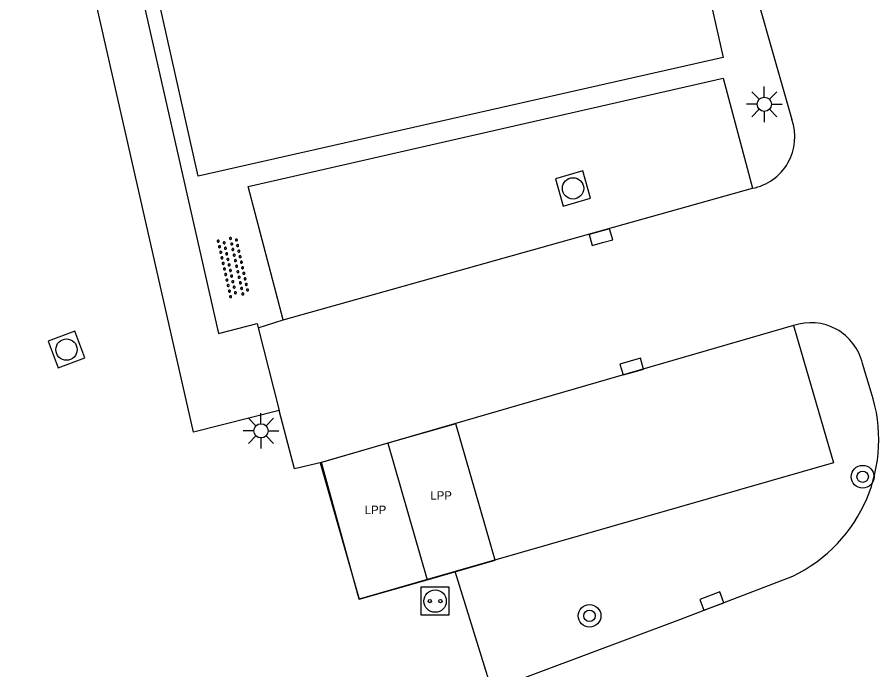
# Model space of a CAD drawing. Extents: x 137999 to 141000, y 397500 to 400501.
# Drawn here: x 138312.22 to 138342.52, y 399235.95 to 399258.89 of the extents above; entities that cross this region are included whole.
import ezdxf

# ---------------------------------------------------------------- set-up
doc = ezdxf.new("R2010")
doc.units = 0
for name, color, linetype in [('bp-grn-parkeervak', 7, 'Continuous'), ('gg-bbg-hoofdgebouw', 7, 'Continuous'), ('gg-knt-verharding', 7, 'Continuous'), ('gg-knt-verharding nz', 7, 'Continuous'), ('gt-grn-groengrens', 7, 'Continuous'), ('gt-symb-boom', 7, 'Continuous'), ('gt-symb-kolk', 7, 'Continuous'), ('gt-symb-laadpunt elektrisch vervoer', 7, 'Continuous'), ('gt-symb-lichtmast', 7, 'Continuous'), ('gt-symb-overige verharding', 7, 'Continuous'), ('gt-symb-rioolschacht', 7, 'Continuous'), ('kenmerkpunt laadpunt parkeerplaats', 7, 'Continuous')]:
    doc.layers.add(name, color=color, linetype=linetype)

# ---------------------------------------------------------------- blocks, each defined once
blk = doc.blocks.new('gt0-RS')
at = {"layer": 'gt-symb-rioolschacht'}
blk.add_lwpolyline([(-0.5, -0.5), (0.5, -0.5), (0.5, 0.5), (-0.5, 0.5)], close=True, dxfattribs=at)
blk.add_circle((0, 0), 0.375, dxfattribs=at)
blk = doc.blocks.new('gt0-KOLK')
at = {"layer": 'gt-symb-kolk'}
blk.add_lwpolyline([(0, 0), (0.375, 0), (0.375, 0.4), (-0.375, 0.4), (-0.375, 0), (0, 0)], dxfattribs=at)
blk = doc.blocks.new('gt0-LMAST')
at = {"layer": 'gt-symb-lichtmast'}
for p, q in [((-0.005, 0.246), (-0.005, 0.621)), ((-0.182, 0.173), (-0.447, 0.438)), ((0.172, 0.173), (0.437, 0.438)), ((-0.255, -0.004), (-0.63, -0.004)), ((-0.182, -0.181), (-0.447, -0.446)), ((-0.005, -0.254), (-0.005, -0.629)), ((0.437, -0.446), (0.172, -0.181)), ((0.245, -0.004), (0.62, -0.004))]:
    blk.add_line(p, q, dxfattribs=at)
blk.add_circle((-0.005, -0.004), 0.25, dxfattribs=at)
blk = doc.blocks.new('gt0-OVH')
at = {"layer": 'gt-symb-overige verharding'}
for points in [[(-0.972, 0.298), (-0.967, 0.308), (-0.965, 0.319), (-0.966, 0.33), (-0.971, 0.34), (-0.978, 0.348), (-0.988, 0.353), (-0.999, 0.355), (-1.01, 0.354), (-1.02, 0.349), (-1.028, 0.342), (-1.033, 0.332), (-1.035, 0.321), (-1.034, 0.31), (-1.029, 0.3), (-1.022, 0.292), (-1.012, 0.287), (-1.001, 0.285), (-0.99, 0.286), (-0.98, 0.291)], [(-0.772, 0.298), (-0.767, 0.308), (-0.765, 0.319), (-0.766, 0.33), (-0.771, 0.34), (-0.778, 0.348), (-0.788, 0.353), (-0.799, 0.355), (-0.81, 0.354), (-0.82, 0.349), (-0.828, 0.342), (-0.833, 0.332), (-0.835, 0.321), (-0.834, 0.31), (-0.829, 0.3), (-0.822, 0.292), (-0.812, 0.287), (-0.801, 0.285), (-0.79, 0.286), (-0.78, 0.291)], [(-0.572, 0.298), (-0.567, 0.308), (-0.565, 0.319), (-0.566, 0.33), (-0.571, 0.34), (-0.578, 0.348), (-0.588, 0.353), (-0.599, 0.355), (-0.61, 0.354), (-0.62, 0.349), (-0.628, 0.342), (-0.633, 0.332), (-0.635, 0.321), (-0.634, 0.31), (-0.629, 0.3), (-0.622, 0.292), (-0.612, 0.287), (-0.601, 0.285), (-0.59, 0.286), (-0.58, 0.291)], [(-0.372, 0.298), (-0.367, 0.308), (-0.365, 0.319), (-0.366, 0.33), (-0.371, 0.34), (-0.378, 0.348), (-0.388, 0.353), (-0.399, 0.355), (-0.41, 0.354), (-0.42, 0.349), (-0.428, 0.342), (-0.433, 0.332), (-0.435, 0.321), (-0.434, 0.31), (-0.429, 0.3), (-0.422, 0.292), (-0.412, 0.287), (-0.401, 0.285), (-0.39, 0.286), (-0.38, 0.291)], [(-0.172, 0.298), (-0.167, 0.308), (-0.165, 0.319), (-0.166, 0.33), (-0.171, 0.34), (-0.178, 0.348), (-0.188, 0.353), (-0.199, 0.355), (-0.21, 0.354), (-0.22, 0.349), (-0.228, 0.342), (-0.233, 0.332), (-0.235, 0.321), (-0.234, 0.31), (-0.229, 0.3), (-0.222, 0.292), (-0.212, 0.287), (-0.201, 0.285), (-0.19, 0.286), (-0.18, 0.291)], [(0.028, 0.298), (0.033, 0.308), (0.035, 0.319), (0.034, 0.33), (0.029, 0.34), (0.022, 0.348), (0.012, 0.353), (0.001, 0.355), (-0.01, 0.354), (-0.02, 0.349), (-0.028, 0.342), (-0.033, 0.332), (-0.035, 0.321), (-0.034, 0.31), (-0.029, 0.3), (-0.022, 0.292), (-0.012, 0.287), (-0.001, 0.285), (0.01, 0.286), (0.02, 0.291)], [(0.228, 0.298), (0.233, 0.308), (0.235, 0.319), (0.234, 0.33), (0.229, 0.34), (0.222, 0.348), (0.212, 0.353), (0.201, 0.355), (0.19, 0.354), (0.18, 0.349), (0.172, 0.342), (0.167, 0.332), (0.165, 0.321), (0.166, 0.31), (0.171, 0.3), (0.178, 0.292), (0.188, 0.287), (0.199, 0.285), (0.21, 0.286), (0.22, 0.291)], [(0.428, 0.298), (0.433, 0.308), (0.435, 0.319), (0.434, 0.33), (0.429, 0.34), (0.422, 0.348), (0.412, 0.353), (0.401, 0.355), (0.39, 0.354), (0.38, 0.349), (0.372, 0.342), (0.367, 0.332), (0.365, 0.321), (0.366, 0.31), (0.371, 0.3), (0.378, 0.292), (0.388, 0.287), (0.399, 0.285), (0.41, 0.286), (0.42, 0.291)], [(0.628, 0.298), (0.633, 0.308), (0.635, 0.319), (0.634, 0.33), (0.629, 0.34), (0.622, 0.348), (0.612, 0.353), (0.601, 0.355), (0.59, 0.354), (0.58, 0.349), (0.572, 0.342), (0.567, 0.332), (0.565, 0.321), (0.566, 0.31), (0.571, 0.3), (0.578, 0.292), (0.588, 0.287), (0.599, 0.285), (0.61, 0.286), (0.62, 0.291)], [(0.828, 0.298), (0.833, 0.308), (0.835, 0.319), (0.834, 0.33), (0.829, 0.34), (0.822, 0.348), (0.812, 0.353), (0.801, 0.355), (0.79, 0.354), (0.78, 0.349), (0.772, 0.342), (0.767, 0.332), (0.765, 0.321), (0.766, 0.31), (0.771, 0.3), (0.778, 0.292), (0.788, 0.287), (0.799, 0.285), (0.81, 0.286), (0.82, 0.291)], [(1.028, 0.298), (1.033, 0.308), (1.035, 0.319), (1.034, 0.33), (1.029, 0.34), (1.022, 0.348), (1.012, 0.353), (1.001, 0.355), (0.99, 0.354), (0.98, 0.349), (0.972, 0.342), (0.967, 0.332), (0.965, 0.321), (0.966, 0.31), (0.971, 0.3), (0.978, 0.292), (0.988, 0.287), (0.999, 0.285), (1.01, 0.286), (1.02, 0.291)], [(-0.872, 0.106), (-0.867, 0.116), (-0.865, 0.126), (-0.866, 0.137), (-0.871, 0.147), (-0.878, 0.156), (-0.888, 0.161), (-0.899, 0.163), (-0.91, 0.162), (-0.92, 0.157), (-0.928, 0.15), (-0.933, 0.14), (-0.935, 0.129), (-0.934, 0.118), (-0.929, 0.108), (-0.922, 0.1), (-0.912, 0.095), (-0.901, 0.092), (-0.89, 0.094), (-0.88, 0.098)], [(-0.672, 0.106), (-0.667, 0.116), (-0.665, 0.126), (-0.666, 0.137), (-0.671, 0.147), (-0.678, 0.156), (-0.688, 0.161), (-0.699, 0.163), (-0.71, 0.162), (-0.72, 0.157), (-0.728, 0.15), (-0.733, 0.14), (-0.735, 0.129), (-0.734, 0.118), (-0.729, 0.108), (-0.722, 0.1), (-0.712, 0.095), (-0.701, 0.092), (-0.69, 0.094), (-0.68, 0.098)], [(-0.472, 0.106), (-0.467, 0.116), (-0.465, 0.126), (-0.466, 0.137), (-0.471, 0.147), (-0.478, 0.156), (-0.488, 0.161), (-0.499, 0.163), (-0.51, 0.162), (-0.52, 0.157), (-0.528, 0.15), (-0.533, 0.14), (-0.535, 0.129), (-0.534, 0.118), (-0.529, 0.108), (-0.522, 0.1), (-0.512, 0.095), (-0.501, 0.092), (-0.49, 0.094), (-0.48, 0.098)], [(-0.272, 0.106), (-0.267, 0.116), (-0.265, 0.126), (-0.266, 0.137), (-0.271, 0.147), (-0.278, 0.156), (-0.288, 0.161), (-0.299, 0.163), (-0.31, 0.162), (-0.32, 0.157), (-0.328, 0.15), (-0.333, 0.14), (-0.335, 0.129), (-0.334, 0.118), (-0.329, 0.108), (-0.322, 0.1), (-0.312, 0.095), (-0.301, 0.092), (-0.29, 0.094), (-0.28, 0.098)], [(-0.072, 0.106), (-0.067, 0.116), (-0.065, 0.126), (-0.066, 0.137), (-0.071, 0.147), (-0.078, 0.156), (-0.088, 0.161), (-0.099, 0.163), (-0.11, 0.162), (-0.12, 0.157), (-0.128, 0.15), (-0.133, 0.14), (-0.135, 0.129), (-0.134, 0.118), (-0.129, 0.108), (-0.122, 0.1), (-0.112, 0.095), (-0.101, 0.092), (-0.09, 0.094), (-0.08, 0.098)], [(0.128, 0.106), (0.133, 0.116), (0.135, 0.126), (0.134, 0.137), (0.129, 0.147), (0.122, 0.156), (0.112, 0.161), (0.101, 0.163), (0.09, 0.162), (0.08, 0.157), (0.072, 0.15), (0.067, 0.14), (0.065, 0.129), (0.066, 0.118), (0.071, 0.108), (0.078, 0.1), (0.088, 0.095), (0.099, 0.092), (0.11, 0.094), (0.12, 0.098)], [(0.328, 0.106), (0.333, 0.116), (0.335, 0.126), (0.334, 0.137), (0.329, 0.147), (0.322, 0.156), (0.312, 0.161), (0.301, 0.163), (0.29, 0.162), (0.28, 0.157), (0.272, 0.15), (0.267, 0.14), (0.265, 0.129), (0.266, 0.118), (0.271, 0.108), (0.278, 0.1), (0.288, 0.095), (0.299, 0.092), (0.31, 0.094), (0.32, 0.098)], [(0.528, 0.106), (0.533, 0.116), (0.535, 0.126), (0.534, 0.137), (0.529, 0.147), (0.522, 0.156), (0.512, 0.161), (0.501, 0.163), (0.49, 0.162), (0.48, 0.157), (0.472, 0.15), (0.467, 0.14), (0.465, 0.129), (0.466, 0.118), (0.471, 0.108), (0.478, 0.1), (0.488, 0.095), (0.499, 0.092), (0.51, 0.094), (0.52, 0.098)], [(0.728, 0.106), (0.733, 0.116), (0.735, 0.126), (0.734, 0.137), (0.729, 0.147), (0.722, 0.156), (0.712, 0.161), (0.701, 0.163), (0.69, 0.162), (0.68, 0.157), (0.672, 0.15), (0.667, 0.14), (0.665, 0.129), (0.666, 0.118), (0.671, 0.108), (0.678, 0.1), (0.688, 0.095), (0.699, 0.092), (0.71, 0.094), (0.72, 0.098)], [(0.928, 0.106), (0.933, 0.116), (0.935, 0.126), (0.934, 0.137), (0.929, 0.147), (0.922, 0.156), (0.912, 0.161), (0.901, 0.163), (0.89, 0.162), (0.88, 0.157), (0.872, 0.15), (0.867, 0.14), (0.865, 0.129), (0.866, 0.118), (0.871, 0.108), (0.878, 0.1), (0.888, 0.095), (0.899, 0.092), (0.91, 0.094), (0.92, 0.098)], [(-0.972, -0.142), (-0.967, -0.132), (-0.965, -0.121), (-0.966, -0.11), (-0.971, -0.1), (-0.978, -0.092), (-0.988, -0.087), (-0.999, -0.085), (-1.01, -0.086), (-1.02, -0.091), (-1.028, -0.098), (-1.033, -0.108), (-1.035, -0.119), (-1.034, -0.13), (-1.029, -0.14), (-1.022, -0.148), (-1.012, -0.153), (-1.001, -0.155), (-0.99, -0.154), (-0.98, -0.149)], [(-0.872, -0.334), (-0.867, -0.324), (-0.865, -0.314), (-0.866, -0.303), (-0.871, -0.293), (-0.878, -0.284), (-0.888, -0.279), (-0.899, -0.277), (-0.91, -0.278), (-0.92, -0.283), (-0.928, -0.29), (-0.933, -0.3), (-0.935, -0.311), (-0.934, -0.322), (-0.929, -0.332), (-0.922, -0.34), (-0.912, -0.345), (-0.901, -0.348), (-0.89, -0.346), (-0.88, -0.342)], [(-0.772, -0.142), (-0.767, -0.132), (-0.765, -0.121), (-0.766, -0.11), (-0.771, -0.1), (-0.778, -0.092), (-0.788, -0.087), (-0.799, -0.085), (-0.81, -0.086), (-0.82, -0.091), (-0.828, -0.098), (-0.833, -0.108), (-0.835, -0.119), (-0.834, -0.13), (-0.829, -0.14), (-0.822, -0.148), (-0.812, -0.153), (-0.801, -0.155), (-0.79, -0.154), (-0.78, -0.149)], [(-0.672, -0.334), (-0.667, -0.324), (-0.665, -0.314), (-0.666, -0.303), (-0.671, -0.293), (-0.678, -0.284), (-0.688, -0.279), (-0.699, -0.277), (-0.71, -0.278), (-0.72, -0.283), (-0.728, -0.29), (-0.733, -0.3), (-0.735, -0.311), (-0.734, -0.322), (-0.729, -0.332), (-0.722, -0.34), (-0.712, -0.345), (-0.701, -0.348), (-0.69, -0.346), (-0.68, -0.342)], [(-0.572, -0.142), (-0.567, -0.132), (-0.565, -0.121), (-0.566, -0.11), (-0.571, -0.1), (-0.578, -0.092), (-0.588, -0.087), (-0.599, -0.085), (-0.61, -0.086), (-0.62, -0.091), (-0.628, -0.098), (-0.633, -0.108), (-0.635, -0.119), (-0.634, -0.13), (-0.629, -0.14), (-0.622, -0.148), (-0.612, -0.153), (-0.601, -0.155), (-0.59, -0.154), (-0.58, -0.149)], [(-0.472, -0.334), (-0.467, -0.324), (-0.465, -0.314), (-0.466, -0.303), (-0.471, -0.293), (-0.478, -0.284), (-0.488, -0.279), (-0.499, -0.277), (-0.51, -0.278), (-0.52, -0.283), (-0.528, -0.29), (-0.533, -0.3), (-0.535, -0.311), (-0.534, -0.322), (-0.529, -0.332), (-0.522, -0.34), (-0.512, -0.345), (-0.501, -0.348), (-0.49, -0.346), (-0.48, -0.342)], [(-0.372, -0.142), (-0.367, -0.132), (-0.365, -0.121), (-0.366, -0.11), (-0.371, -0.1), (-0.378, -0.092), (-0.388, -0.087), (-0.399, -0.085), (-0.41, -0.086), (-0.42, -0.091), (-0.428, -0.098), (-0.433, -0.108), (-0.435, -0.119), (-0.434, -0.13), (-0.429, -0.14), (-0.422, -0.148), (-0.412, -0.153), (-0.401, -0.155), (-0.39, -0.154), (-0.38, -0.149)], [(-0.272, -0.334), (-0.267, -0.324), (-0.265, -0.314), (-0.266, -0.303), (-0.271, -0.293), (-0.278, -0.284), (-0.288, -0.279), (-0.299, -0.277), (-0.31, -0.278), (-0.32, -0.283), (-0.328, -0.29), (-0.333, -0.3), (-0.335, -0.311), (-0.334, -0.322), (-0.329, -0.332), (-0.322, -0.34), (-0.312, -0.345), (-0.301, -0.348), (-0.29, -0.346), (-0.28, -0.342)], [(-0.172, -0.142), (-0.167, -0.132), (-0.165, -0.121), (-0.166, -0.11), (-0.171, -0.1), (-0.178, -0.092), (-0.188, -0.087), (-0.199, -0.085), (-0.21, -0.086), (-0.22, -0.091), (-0.228, -0.098), (-0.233, -0.108), (-0.235, -0.119), (-0.234, -0.13), (-0.229, -0.14), (-0.222, -0.148), (-0.212, -0.153), (-0.201, -0.155), (-0.19, -0.154), (-0.18, -0.149)], [(-0.072, -0.334), (-0.067, -0.324), (-0.065, -0.314), (-0.066, -0.303), (-0.071, -0.293), (-0.078, -0.284), (-0.088, -0.279), (-0.099, -0.277), (-0.11, -0.278), (-0.12, -0.283), (-0.128, -0.29), (-0.133, -0.3), (-0.135, -0.311), (-0.134, -0.322), (-0.129, -0.332), (-0.122, -0.34), (-0.112, -0.345), (-0.101, -0.348), (-0.09, -0.346), (-0.08, -0.342)], [(0.028, -0.142), (0.033, -0.132), (0.035, -0.121), (0.034, -0.11), (0.029, -0.1), (0.022, -0.092), (0.012, -0.087), (0.001, -0.085), (-0.01, -0.086), (-0.02, -0.091), (-0.028, -0.098), (-0.033, -0.108), (-0.035, -0.119), (-0.034, -0.13), (-0.029, -0.14), (-0.022, -0.148), (-0.012, -0.153), (-0.001, -0.155), (0.01, -0.154), (0.02, -0.149)], [(0.128, -0.334), (0.133, -0.324), (0.135, -0.314), (0.134, -0.303), (0.129, -0.293), (0.122, -0.284), (0.112, -0.279), (0.101, -0.277), (0.09, -0.278), (0.08, -0.283), (0.072, -0.29), (0.067, -0.3), (0.065, -0.311), (0.066, -0.322), (0.071, -0.332), (0.078, -0.34), (0.088, -0.345), (0.099, -0.348), (0.11, -0.346), (0.12, -0.342)], [(0.228, -0.142), (0.233, -0.132), (0.235, -0.121), (0.234, -0.11), (0.229, -0.1), (0.222, -0.092), (0.212, -0.087), (0.201, -0.085), (0.19, -0.086), (0.18, -0.091), (0.172, -0.098), (0.167, -0.108), (0.165, -0.119), (0.166, -0.13), (0.171, -0.14), (0.178, -0.148), (0.188, -0.153), (0.199, -0.155), (0.21, -0.154), (0.22, -0.149)], [(0.328, -0.334), (0.333, -0.324), (0.335, -0.314), (0.334, -0.303), (0.329, -0.293), (0.322, -0.284), (0.312, -0.279), (0.301, -0.277), (0.29, -0.278), (0.28, -0.283), (0.272, -0.29), (0.267, -0.3), (0.265, -0.311), (0.266, -0.322), (0.271, -0.332), (0.278, -0.34), (0.288, -0.345), (0.299, -0.348), (0.31, -0.346), (0.32, -0.342)], [(0.428, -0.142), (0.433, -0.132), (0.435, -0.121), (0.434, -0.11), (0.429, -0.1), (0.422, -0.092), (0.412, -0.087), (0.401, -0.085), (0.39, -0.086), (0.38, -0.091), (0.372, -0.098), (0.367, -0.108), (0.365, -0.119), (0.366, -0.13), (0.371, -0.14), (0.378, -0.148), (0.388, -0.153), (0.399, -0.155), (0.41, -0.154), (0.42, -0.149)], [(0.528, -0.334), (0.533, -0.324), (0.535, -0.314), (0.534, -0.303), (0.529, -0.293), (0.522, -0.284), (0.512, -0.279), (0.501, -0.277), (0.49, -0.278), (0.48, -0.283), (0.472, -0.29), (0.467, -0.3), (0.465, -0.311), (0.466, -0.322), (0.471, -0.332), (0.478, -0.34), (0.488, -0.345), (0.499, -0.348), (0.51, -0.346), (0.52, -0.342)], [(0.628, -0.142), (0.633, -0.132), (0.635, -0.121), (0.634, -0.11), (0.629, -0.1), (0.622, -0.092), (0.612, -0.087), (0.601, -0.085), (0.59, -0.086), (0.58, -0.091), (0.572, -0.098), (0.567, -0.108), (0.565, -0.119), (0.566, -0.13), (0.571, -0.14), (0.578, -0.148), (0.588, -0.153), (0.599, -0.155), (0.61, -0.154), (0.62, -0.149)], [(0.728, -0.334), (0.733, -0.324), (0.735, -0.314), (0.734, -0.303), (0.729, -0.293), (0.722, -0.284), (0.712, -0.279), (0.701, -0.277), (0.69, -0.278), (0.68, -0.283), (0.672, -0.29), (0.667, -0.3), (0.665, -0.311), (0.666, -0.322), (0.671, -0.332), (0.678, -0.34), (0.688, -0.345), (0.699, -0.348), (0.71, -0.346), (0.72, -0.342)], [(0.828, -0.142), (0.833, -0.132), (0.835, -0.121), (0.834, -0.11), (0.829, -0.1), (0.822, -0.092), (0.812, -0.087), (0.801, -0.085), (0.79, -0.086), (0.78, -0.091), (0.772, -0.098), (0.767, -0.108), (0.765, -0.119), (0.766, -0.13), (0.771, -0.14), (0.778, -0.148), (0.788, -0.153), (0.799, -0.155), (0.81, -0.154), (0.82, -0.149)], [(0.928, -0.334), (0.933, -0.324), (0.935, -0.314), (0.934, -0.303), (0.929, -0.293), (0.922, -0.284), (0.912, -0.279), (0.901, -0.277), (0.89, -0.278), (0.88, -0.283), (0.872, -0.29), (0.867, -0.3), (0.865, -0.311), (0.866, -0.322), (0.871, -0.332), (0.878, -0.34), (0.888, -0.345), (0.899, -0.348), (0.91, -0.346), (0.92, -0.342)], [(1.028, -0.142), (1.033, -0.132), (1.035, -0.121), (1.034, -0.11), (1.029, -0.1), (1.022, -0.092), (1.012, -0.087), (1.001, -0.085), (0.99, -0.086), (0.98, -0.091), (0.972, -0.098), (0.967, -0.108), (0.965, -0.119), (0.966, -0.13), (0.971, -0.14), (0.978, -0.148), (0.988, -0.153), (0.999, -0.155), (1.01, -0.154), (1.02, -0.149)]]:
    blk.add_lwpolyline(points, close=True, dxfattribs=at)
blk = doc.blocks.new('gt0-BOOM')
at = {"layer": 'gt-symb-boom'}
for radius in [0.4, 0.2]:
    blk.add_circle((0, 0), radius, dxfattribs=at)
blk = doc.blocks.new('gt0-LEV')
at = {"layer": 'gt-symb-laadpunt elektrisch vervoer'}
blk.add_lwpolyline([(-0.486, 0.501), (0.486, 0.501), (0.486, -0.499), (-0.486, -0.499)], close=True, dxfattribs=at)
for centre, radius in [((0, 0), 0.393), ((-0.186, 0), 0.0566), ((0.186, 0), 0.0566)]:
    blk.add_circle(centre, radius, dxfattribs=at)

msp = doc.modelspace()

# ---------------------------------------------------------------- linework, layer by layer
at = {"layer": 'bp-grn-parkeervak'}
msp.add_line((138325.262, 399243.911), (138326.64, 399239.117), dxfattribs=at)
for points in [[(138326.64, 399239.117), (138329.028, 399239.804), (138327.65, 399244.597), (138325.262, 399243.911)], [(138325.262, 399243.911), (138322.874, 399243.224), (138324.252, 399238.431), (138326.64, 399239.117)]]:
    msp.add_lwpolyline(points, dxfattribs=at)
at = {"layer": 'gg-bbg-hoofdgebouw'}
msp.add_lwpolyline([(138335.62, 399275.09), (138335.51, 399275.57), (138333.09, 399275.03), (138337.05, 399257.48), (138318.59, 399253.3), (138314.66, 399270.83), (138308.28, 399269.44), (138303.154, 399280.598)], dxfattribs=at)
at = {"layer": 'gg-knt-verharding'}
for p, q in [((138320.697, 399247.971), (138321.574, 399248.252)), ((138320.697, 399247.971), (138321.432, 399245.062)), ((138342.255, 399245.709), (138341.948, 399246.719))]:
    msp.add_line(p, q, dxfattribs=at)
for points in [[(138303.154, 399280.598), (138302.682, 399280.381), (138307.997, 399268.838), (138314.217, 399270.224), (138319.297, 399247.77), (138320.658, 399248.125), (138320.697, 399247.971)], [(138335.62, 399275.09), (138333.943, 399274.641), (138339.47, 399255.295)], [(138321.432, 399245.062), (138318.42, 399244.301), (138312.983, 399268.267), (138307.053, 399266.923)], [(138321.574, 399248.252), (138320.345, 399252.941), (138337.057, 399256.745), (138338.079, 399252.876)], [(138339.523, 399248.049), (138340.932, 399243.226), (138327.627, 399239.401)], [(138322.921, 399243.238), (138321.977, 399243.008), (138321.432, 399245.062)], [(138327.627, 399239.401), (138324.252, 399238.431), (138322.921, 399243.238)], [(138328.912, 399235.243), (138335.53, 399237.721), (138339.499, 399239.244)]]:
    msp.add_lwpolyline(points, dxfattribs=at)
for centre, radius, start, end in [((138337.727, 399254.688), 1.846, 281.0048, 19.1947), ((138340.135, 399246.29), 1.863, 13.3274, 109.1871), ((138337.21, 399244.04), 5.314, 295.5187, 18.3047)]:
    msp.add_arc(centre, radius, start, end, dxfattribs=at)
at = {"layer": 'gg-knt-verharding nz'}
for p, q in [((138321.574, 399248.252), (138338.079, 399252.876)), ((138339.523, 399248.049), (138325.26, 399243.916)), ((138325.26, 399243.916), (138322.921, 399243.238))]:
    msp.add_line(p, q, dxfattribs=at)
at = {"layer": 'gt-grn-groengrens'}
msp.add_line((138328.912, 399235.243), (138327.627, 399239.401), dxfattribs=at)

# ---------------------------------------------------------------- block references
at = {"layer": 'gt-symb-boom'}
for p in [(138341.958, 399242.736), (138332.352, 399237.846)]:
    msp.add_blockref('gt0-BOOM', p, dxfattribs=at)
at = {"layer": 'gt-symb-kolk'}
for p, rotation in [((138332.805, 399250.967), 15.66210634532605), ((138333.89, 399246.418), 16.13420459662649), ((138336.725, 399238.179), 20.173944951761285)]:
    msp.add_blockref('gt0-KOLK', p, dxfattribs=dict(at, rotation=rotation))
at = {"layer": 'gt-symb-laadpunt elektrisch vervoer'}
msp.add_blockref('gt0-LEV', (138326.921, 399238.364), dxfattribs=at)
at = {"layer": 'gt-symb-lichtmast'}
for p in [(138338.504, 399255.834), (138320.802, 399244.354)]:
    msp.add_blockref('gt0-LMAST', p, dxfattribs=at)
at = {"layer": 'gt-symb-overige verharding', "rotation": 102.59095061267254}
msp.add_blockref('gt0-OVH', (138319.824, 399250.112), dxfattribs=at)
at = {"layer": 'gt-symb-rioolschacht'}
for p, rotation in [((138331.771, 399252.873), 16.13420459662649), ((138313.957, 399247.206), -69.44395478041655)]:
    msp.add_blockref('gt0-RS', p, dxfattribs=dict(at, rotation=rotation))

# ---------------------------------------------------------------- texts
at = {"layer": 'kenmerkpunt laadpunt parkeerplaats'}
for p in [(138326.754, 399241.926), (138324.445, 399241.421)]:
    msp.add_text('LPP', height=0.3, dxfattribs=at).set_placement(p)

doc.saveas('drawing.dxf')
